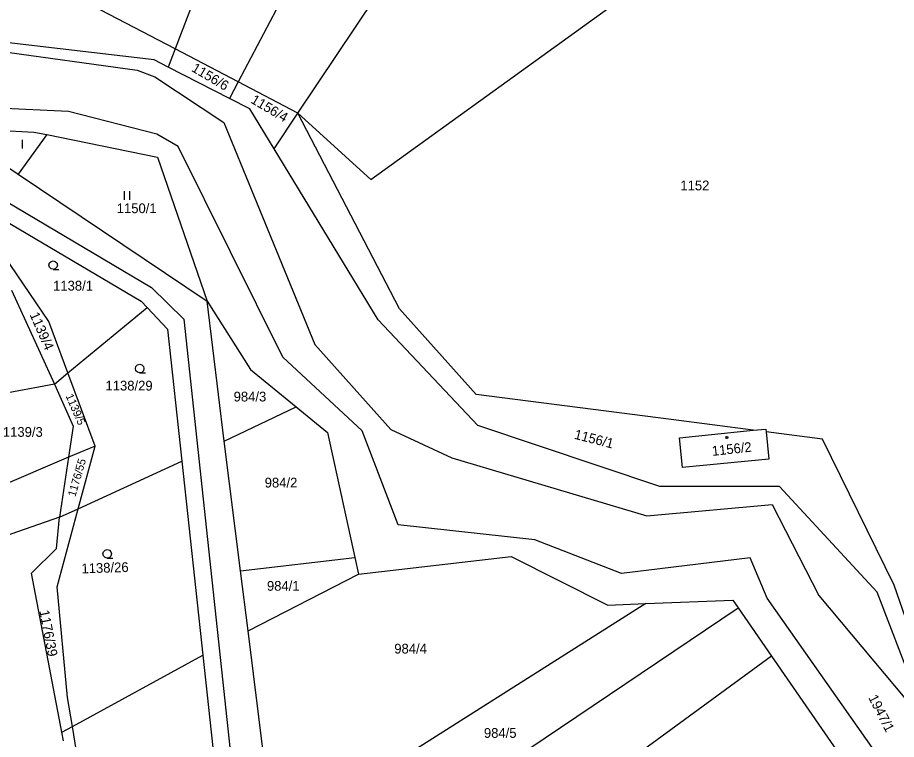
# Model space of a CAD drawing. Extents: x -621797 to -620972, y -1175539 to -1174697.
# Drawn here: x -621507.6 to -621354.5, y -1175256.3 to -1175130.5 of the extents above; entities that cross this region are included whole.
import ezdxf

# ---------------------------------------------------------------- set-up
doc = ezdxf.new("R2010")
doc.units = 0
for name, color, linetype in [('INZ mimo EON - nadz', 7, 'Continuous'), ('Rozvod plynu EON', 7, 'Continuous'), ('SDEL EON', 7, 'Continuous'), ('SDEL EON - popis', 7, 'Continuous'), ('Silnoproud EON', 7, 'Continuous'), ('Silnoproud EON - popis', 7, 'Continuous')]:
    doc.layers.add(name, color=color, linetype=linetype)

msp = doc.modelspace()

# ---------------------------------------------------------------- linework, layer by layer
at = {"layer": 'Rozvod plynu EON'}
msp.add_lwpolyline([(-621383.92, -1175203.56), (-621383.83, -1175203.71), (-621383.92, -1175203.86), (-621384.1, -1175203.86), (-621384.19, -1175203.71), (-621384.1, -1175203.56)], close=True, dxfattribs=at)
at = {"layer": 'SDEL EON'}
for p, q in [((-621506.75, -1175153.37), (-621506.75, -1175151.87)), ((-621489.06, -1175160.79), (-621489.06, -1175162.29)), ((-621488.06, -1175162.29), (-621488.06, -1175160.79))]:
    msp.add_line(p, q, dxfattribs=at)
for points in [[(-621501.42, -1175174.4), (-621501.8, -1175174.3), (-621502.07, -1175174.03), (-621502.17, -1175173.66), (-621502.07, -1175173.29), (-621501.8, -1175173.02), (-621501.43, -1175172.92), (-621501.06, -1175173.02), (-621500.79, -1175173.29), (-621500.69, -1175173.67), (-621500.79, -1175174.05), (-621501.06, -1175174.32), (-621501.44, -1175174.42), (-621500.44, -1175174.42)], [(-621486.34, -1175192.44), (-621486.72, -1175192.34), (-621486.99, -1175192.07), (-621487.09, -1175191.7), (-621486.99, -1175191.33), (-621486.72, -1175191.06), (-621486.35, -1175190.96), (-621485.98, -1175191.06), (-621485.71, -1175191.33), (-621485.61, -1175191.71), (-621485.71, -1175192.09), (-621485.98, -1175192.36), (-621486.36, -1175192.46), (-621485.36, -1175192.46)], [(-621491.99, -1175224.72), (-621492.37, -1175224.62), (-621492.64, -1175224.35), (-621492.74, -1175223.98), (-621492.64, -1175223.61), (-621492.37, -1175223.34), (-621492, -1175223.24), (-621491.63, -1175223.34), (-621491.36, -1175223.61), (-621491.26, -1175223.99), (-621491.36, -1175224.37), (-621491.63, -1175224.64), (-621492.01, -1175224.74), (-621491.01, -1175224.74)]]:
    msp.add_lwpolyline(points, dxfattribs=at)
at = {"layer": 'SDEL EON - popis'}
for p, q in [((-621513.39, -1175136.05), (-621486.76, -1175139.69)), ((-621486.76, -1175139.69), (-621483.71, -1175140.86)), ((-621483.71, -1175140.86), (-621471.7, -1175148.83)), ((-621498.76, -1175146.88), (-621517.96, -1175146.05)), ((-621483.36, -1175150.85), (-621498.76, -1175146.88)), ((-621471.7, -1175148.83), (-621455.83, -1175187.53)), ((-621479.67, -1175153), (-621483.36, -1175150.85)), ((-621461.42, -1175189.71), (-621479.67, -1175153)), ((-621455.83, -1175187.53), (-621442.6, -1175202.32)), ((-621447.6, -1175202.55), (-621461.42, -1175189.71)), ((-621441.31, -1175218.95), (-621447.6, -1175202.55)), ((-621442.6, -1175202.32), (-621431.93, -1175207.24)), ((-621431.93, -1175207.24), (-621397.96, -1175217.34)), ((-621397.96, -1175217.34), (-621376.15, -1175215.4)), ((-621376.15, -1175215.4), (-621368.01, -1175231.22)), ((-621417.49, -1175221.56), (-621441.31, -1175218.95)), ((-621402.36, -1175227.42), (-621417.49, -1175221.56)), ((-621379.95, -1175224.65), (-621402.36, -1175227.42)), ((-621377, -1175231.72), (-621379.95, -1175224.65)), ((-621368.01, -1175231.22), (-621343.71, -1175260.26)), ((-621356.71, -1175260.51), (-621377, -1175231.72))]:
    msp.add_line(p, q, dxfattribs=at)
at = {"layer": 'Silnoproud EON'}
for p, q in [((-621449.39, -1175055.82), (-621480.19, -1175136)), ((-621430.45, -1175067.98), (-621469.21, -1175141.74)), ((-621458.77, -1175147.2), (-621435.42, -1175112.17)), ((-621446.08, -1175158.75), (-621389.63, -1175118.02)), ((-621583.73, -1175118.84), (-621484.26, -1175177.55)), ((-621480.19, -1175136), (-621505.23, -1175122.91)), ((-621483.82, -1175137.93), (-621512.68, -1175134.5)), ((-621480.19, -1175136), (-621481.41, -1175139.16)), ((-621469.21, -1175141.74), (-621480.19, -1175136)), ((-621481.41, -1175139.16), (-621483.82, -1175137.93)), ((-621470.72, -1175144.62), (-621481.41, -1175139.16)), ((-621469.21, -1175141.74), (-621470.72, -1175144.62)), ((-621458.77, -1175147.2), (-621469.21, -1175141.74)), ((-621467.14, -1175146.45), (-621470.72, -1175144.62)), ((-621462.91, -1175153.41), (-621467.14, -1175146.45)), ((-621462.91, -1175153.41), (-621458.77, -1175147.2)), ((-621458.77, -1175147.2), (-621446.08, -1175158.75)), ((-621441.09, -1175181.28), (-621458.77, -1175147.2)), ((-621519.63, -1175149.69), (-621507.5, -1175157.84)), ((-621519.63, -1175149.69), (-621504.77, -1175150.48)), ((-621504.77, -1175150.48), (-621502.55, -1175150.93)), ((-621502.55, -1175150.93), (-621507.5, -1175157.84)), ((-621502.55, -1175150.93), (-621483.22, -1175154.85)), ((-621444.79, -1175183.23), (-621462.91, -1175153.41)), ((-621483.22, -1175154.85), (-621474.58, -1175179.98)), ((-621507.5, -1175157.84), (-621474.58, -1175179.98)), ((-621509.98, -1175165.83), (-621486.07, -1175179.93)), ((-621502.15, -1175183.5), (-621512.49, -1175168.37)), ((-621508.68, -1175178.04), (-621501.21, -1175194.41)), ((-621484.26, -1175177.55), (-621478.66, -1175183.1)), ((-621498.84, -1175192.45), (-621485.04, -1175181.03)), ((-621486.07, -1175179.93), (-621485.04, -1175181.03)), ((-621485.04, -1175181.03), (-621481.49, -1175184.81)), ((-621474.58, -1175179.98), (-621467.01, -1175191.89)), ((-621471.64, -1175204.33), (-621474.58, -1175179.98)), ((-621427.73, -1175196.24), (-621441.09, -1175181.28)), ((-621498.84, -1175192.45), (-621502.15, -1175183.5)), ((-621478.66, -1175183.1), (-621463.62, -1175323.23)), ((-621427.43, -1175201.62), (-621444.79, -1175183.23)), ((-621481.49, -1175184.81), (-621479, -1175207.83)), ((-621501.21, -1175194.41), (-621498.84, -1175192.45)), ((-621494.13, -1175205.2), (-621498.84, -1175192.45)), ((-621467.01, -1175191.89), (-621459.1, -1175198.34)), ((-621501.21, -1175194.41), (-621512.39, -1175196.52)), ((-621501.21, -1175194.41), (-621497.92, -1175201.71)), ((-621393.72, -1175200.59), (-621427.73, -1175196.24)), ((-621471.64, -1175204.33), (-621459.1, -1175198.34)), ((-621459.1, -1175198.34), (-621453.59, -1175202.83)), ((-621379.42, -1175202.45), (-621393.72, -1175200.59)), ((-621497.92, -1175201.71), (-621498.74, -1175207.15)), ((-621395.73, -1175212.23), (-621427.43, -1175201.62)), ((-621392.26, -1175203.76), (-621379.42, -1175202.45)), ((-621379.42, -1175202.45), (-621377.24, -1175202.23)), ((-621377.24, -1175202.23), (-621377.19, -1175202.74)), ((-621453.59, -1175202.83), (-621448.83, -1175224.6)), ((-621391.73, -1175208.93), (-621392.26, -1175203.76)), ((-621367.39, -1175204.02), (-621377.19, -1175202.74)), ((-621377.19, -1175202.74), (-621376.73, -1175207.47)), ((-621354.87, -1175229.42), (-621367.39, -1175204.02)), ((-621494.13, -1175205.2), (-621498.74, -1175207.15)), ((-621497.08, -1175216.14), (-621494.13, -1175205.2)), ((-621468.76, -1175226.92), (-621471.64, -1175204.33)), ((-621498.74, -1175207.15), (-621517.81, -1175215.24)), ((-621498.74, -1175207.15), (-621500.3, -1175217.61)), ((-621497.08, -1175216.14), (-621479, -1175207.83)), ((-621479, -1175207.83), (-621475.34, -1175241.65)), ((-621376.73, -1175207.47), (-621391.73, -1175208.93)), ((-621374.86, -1175212.27), (-621395.73, -1175212.23)), ((-621357.81, -1175230.66), (-621374.86, -1175212.27)), ((-621500.74, -1175229.72), (-621497.08, -1175216.14)), ((-621500.3, -1175217.61), (-621497.08, -1175216.14)), ((-621500.3, -1175217.61), (-621521.27, -1175224.85)), ((-621500.87, -1175223.07), (-621500.3, -1175217.61)), ((-621505.18, -1175227.34), (-621500.87, -1175223.07)), ((-621468.76, -1175226.92), (-621448.83, -1175224.6)), ((-621448.83, -1175224.6), (-621448.19, -1175227.53)), ((-621448.19, -1175227.53), (-621421.59, -1175224.44)), ((-621421.59, -1175224.44), (-621404.76, -1175232.92)), ((-621467.46, -1175237.38), (-621468.76, -1175226.92)), ((-621499.9, -1175255.06), (-621505.18, -1175227.34)), ((-621467.46, -1175237.38), (-621448.19, -1175227.53)), ((-621498.94, -1175248.99), (-621500.74, -1175229.72)), ((-621349.1, -1175246.19), (-621354.87, -1175229.42)), ((-621351.49, -1175247.14), (-621357.81, -1175230.66)), ((-621398.14, -1175232.66), (-621462.97, -1175273.64)), ((-621404.76, -1175232.92), (-621398.14, -1175232.66)), ((-621398.14, -1175232.66), (-621382.99, -1175232.05)), ((-621382.99, -1175232.05), (-621382.08, -1175233.36)), ((-621461.34, -1175286.78), (-621382.08, -1175233.36)), ((-621382.08, -1175233.36), (-621376.22, -1175241.83)), ((-621462.97, -1175273.64), (-621467.46, -1175237.38)), ((-621498.08, -1175254.07), (-621475.34, -1175241.65)), ((-621475.34, -1175241.65), (-621471.35, -1175278.54)), ((-621376.22, -1175241.83), (-621459.4, -1175302.44)), ((-621376.22, -1175241.83), (-621363.21, -1175260.63)), ((-621498.08, -1175254.07), (-621498.94, -1175248.99)), ((-621499.9, -1175255.06), (-621498.08, -1175254.07)), ((-621491.93, -1175290.48), (-621498.08, -1175254.07)), ((-621499.61, -1175256.57), (-621499.9, -1175255.06))]:
    msp.add_line(p, q, dxfattribs=at)

# ---------------------------------------------------------------- texts
at = {"layer": 'INZ mimo EON - nadz'}
msp.add_text('1947/1', height=1.7, rotation=297.02132, dxfattribs=at).set_placement((-621359.422, -1175249.03))
at = {"layer": 'Silnoproud EON - popis'}
for s, height, rotation, p in [('1156/6', 1.7, 329.39344, (-621477.452, -1175139.8)), ('1156/4', 1.7, 329.39344, (-621467.132, -1175145.31)), ('1139/4', 1.7, 293.41169, (-621505.554, -1175182.29)), ('1139/5', 1.4, 293.41169, (-621499.292, -1175196.447)), ('1156/1', 1.7, 345.60814, (-621410.74, -1175203.908)), ('1156/2', 1.7, 6.30254, (-621386.54, -1175206.927)), ('1176/55', 1.4, 73.79696, (-621497.56, -1175214.129)), ('1138/26', 1.7, 1.77617, (-621496.467, -1175227.388)), ('1176/39', 1.7, 280.80662, (-621503.826, -1175233.926))]:
    msp.add_text(s, height=height, rotation=rotation, dxfattribs=at).set_placement(p)
for s, p in [('1152', (-621392.127, -1175160.64)), ('1150/1', (-621490.347, -1175164.62)), ('1138/1', (-621501.437, -1175178.11)), ('1138/29', (-621492.307, -1175195.52)), ('984/3', (-621469.973, -1175197.43)), ('1139/3', (-621510.187, -1175203.59)), ('984/2', (-621464.563, -1175212.42)), ('984/1', (-621464.173, -1175230.41)), ('984/4', (-621441.983, -1175241.35)), ('984/5', (-621426.363, -1175256.04))]:
    msp.add_text(s, height=1.7, dxfattribs=at).set_placement(p)

doc.saveas('drawing.dxf')
